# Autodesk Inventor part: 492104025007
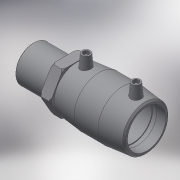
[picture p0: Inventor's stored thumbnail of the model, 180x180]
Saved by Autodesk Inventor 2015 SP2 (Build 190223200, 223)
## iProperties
Created: 2017-06
Part Number: 492104025007
Material: Generic
Description: PLASSON Male Transition Coupler 25 x 3/4"
Document SubType Name: Modeling
Designer: KIM
Mass: 60.1478 g
Surface Area: 248.954 cm^2
Volume: 60.1478 cm^3
Density: 1 g/cm^3
Appearance: Default
Author: KIM
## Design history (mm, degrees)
derived "492104.ipt"
feature "Solid1::492104.ipt"
tag "TaggingFeature1"
body "Solid1"
other parameters: "d0" = 82, "d1" = 25, "d2" = 36, "d4" = 27.33333, "d5" = 32.4, "d6" = 23.75, "d7" = 25, "d8" = 168 deg, "d10" = 16, "d11" = 5.33333, "d29" = 37, "d30" = 14, "d31" = 28.7, "d34" = 5 deg, "d41" = 4, "d42" = 14, "d43" = 0, "d48" = 3, "d49" = 0, "d57" = 19, "d58" = 26.441, "d59" = 21.1528, "d60" = 26.1, "d61" = 36, "d62" = 0.52882, "d65" = 1.08, "d70" = 0.1, "d71" = 29, "d72" = 7.25, "d73" = 16, "d75" = 0, "d_" = 25, "L_" = 111, "D_1" = 36, "A_" = 37, "d_2" = 12, "L_2" = 29, "D_" = 19, "R_" = 26.441
